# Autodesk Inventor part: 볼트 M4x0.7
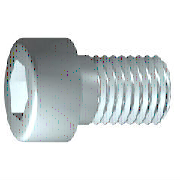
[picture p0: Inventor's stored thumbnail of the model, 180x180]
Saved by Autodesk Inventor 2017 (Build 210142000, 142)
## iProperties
IsCustomPart: 0
Created: 2015-12
Part Number: 볼트 M4x0.7
Material: 강철, 연강
Description: 6각머리 태핑 나사
Document SubType Name: Modeling
Standard: KS B 1003
Designer: mdu
Standards Organization: KS
Language: ko-KR
Size Designation: M 4 x 12
Categories: <MemberInstance><Categories><Category DisplayName="조임쇠" InternalName="e4da775c-781d-43d5-af7c-5136215cf5a6" Mnemonic="FSTN"><Category DisplayName="볼트" InternalN
Density: 1 g/cm^3
Appearance: 강철
Author: mdu
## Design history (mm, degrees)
sketch "스케치1"
  geometry: L1 (-1, 0)-(12, 0); L2 (12, 0)-(12, 2); L3 (12, 2)-(1.75, 2); L4 (1.75, 2)-(1.32, 2); L5 (1.32, 2)-(0, 2); L6 (0, 2)-(0, 3.5); L7 (0, 3.5)-(-4, 3.5); L8 (-4, 3.5)-(-4, 1.732); L9 (-4, 1.732)-(-2, 1.732); L10 (-2, 1.732)-(-1, 0); L11 (-7.2, 0)-(15.2, 0) reference; L12 (0, -0.7)-(0, 4.2) reference; L13 (1.75, 2)-(0, 2)
  constraints: 22 end point, 6 parallel, 2 collinear, 2 perpendicular, 1 horizontal, 1 point on line
  dimensions: "d1" = 10.25 distance from line of L3.end L2 (= GEL); "d2" = 0.42952 distance of L4.end L3.end (computed from GAL); "d3" = 4 distance between parallel lines of L8 L6 (= KOH); "d4" = 2 distance of L8.end L9.end (= INTI); "d5" = 60 deg angle of L10 L1; "d6" = 4 diameter of L3 L1 (= GD); "d7" = 4 diameter of L5 L1 (= BDM); "d8" = 3.4641 diameter of L9 L1 (= 1.1547 x SW); "d9" = 7 diameter of L7 L1 (= KOD); "d26" = 12 distance between parallel lines of L12 L2 (= NLG)
revolve "본체" sketch "스케치1" stored, may be unused: angle "d10" = 90 deg
sketch "스케치2"
  geometry: L1 (0, -4.9)-(0, 4.9) reference; L2 (-4.9, 0)-(4.9, 0) reference; L3 (1.732, 0)-(0.866, -1.5); L4 (0.866, -1.5)-(-0.866, -1.5); L5 (-0.866, -1.5)-(-1.732, 0); L6 (-1.732, 0)-(-0.866, 1.5); L7 (-0.866, 1.5)-(0.866, 1.5); L8 (0.866, 1.5)-(1.732, 0); 2 further points
  constraints: 12 end point, 1 coincident, 1 horizontal alignment, 1 point on line, 12 other
extrude "슬롯" join sketch "스케치2" stored distance "d11" = 10; taper "d12" = 0 deg
workplane "Work Plane1"
fillet "Fillet2" dims "d30" = 0.1 (= R)
body "Solid1"
fillet "모깎기1" dims "d17" = 0.4 (= RR)
feature "스레드" dims "d13" = 10.25 (= GEL), "d14" = 0
chamfer "모따기1" distance "d15" = 0.42941 (= -0.5 x SPD + 0.5 x GD); stored, may be unused: second distance "d16" = 0.42941 (= GUL), angle "d27" = 45 deg
other parameters: "GD" = 4 (= NND) [user parameter; used in 2 equation terms], "NLG" = 12 [user parameter; used in 1 equation term], "GEL" = 10.25 [user parameter; used in 2 equation terms], "KOD" = 7 [user parameter; used in 1 equation term], "KOH" = 4 [user parameter; used in 1 equation term], "INTI" = 2 [user parameter; used in 1 equation term], "GAL" = 0.42941 (= 0.61345 x PTC) [user parameter; used in 1 equation term], "GUL" = 0.42941 (= 0.61345 x PTC) [user parameter; used in 1 equation term], "BDM" = 4 (= NND) [user parameter; used in 1 equation term], "SW" = 3 [user parameter; used in 2 equation terms], "RR" = 0.4 [user parameter; used in 1 equation term], "SPD" = 3.14117 (= NND - 1.2269 x PTC) [user parameter; used in 1 equation term], "d19" = 0, "d28" = 0, "d29" = 0, "R" = 0.1 [user parameter; used in 1 equation term], "PHH" = 0.2 [user parameter], "GD1" = 3.14117 (= THREADDIA - 1.2269 x PTC) [user parameter], "THREADDIA" = 4 [user parameter; used in 1 equation term], "FAWI" = 45 deg [user parameter], "TPU" = 14.28571 (computed from PTC) [user parameter], "PTC" = 0.7 [user parameter; used in 5 equation terms], "NND" = 4 [user parameter; used in 3 equation terms], "TOA" = 30 deg [user parameter], "E0" = 3.465 (= 1.155 x SW) [user parameter]
